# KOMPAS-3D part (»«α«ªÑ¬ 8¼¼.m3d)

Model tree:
1. Эскиз:1
2. Операция выдавливания:1
     Расстояние 1 = 8
3. Эскиз:2
4. Операция выдавливания:2
     Расстояние 1 = 1
5. Эскиз:3
6. Операция выдавливания:3
     Расстояние 1 = 2.5; Угол 1 = 8
7. Эскиз:4
8. Вырезать элемент выдавливания:1
     Расстояние 1 = 20
9. Эскиз:5
10. Вырезать элемент выдавливания:2
     Расстояние 1 = 3; Угол 1 = 19
11. Скругление:1
     Радиус = 1
12. Скругление:2
     Радиус = 1
13. Скругление:3
     Радиус = 1
14. Эскиз:6
15. Эскиз:7
16. Вырезать элемент выдавливания:3
     Расстояние 2 = 30; Расстояние 1 = 60
17. Эскиз:8
18. Вырезать элемент выдавливания:4
     Расстояние 2 = 30; Расстояние 1 = 60
19. Эскиз:9
20. Операция выдавливания:4
     Расстояние 1 = 10; Расстояние 2 = 62
21. Эскиз:10
22. Вырезать элемент выдавливания:5
     Расстояние 2 = 30; Расстояние 1 = 60
23. Скругление:4
     Радиус = 2
24. Скругление:5
     Радиус = 2
25. Эскиз:11
26. Вырезать элемент выдавливания:6
     Расстояние 1 = 10
27. Эскиз:12
28. Вырезать элемент выдавливания:7
     Расстояние 1 = 2.5; Угол 1 = 3
29. Эскиз:13
30. Вырезать элемент выдавливания:8
     Расстояние 2 = 40; Расстояние 1 = 30
31. Эскиз:14
32. Операция выдавливания:5
     Расстояние 1 = 10
33. Операция выдавливания:6
     Расстояние 1 = 2.5; Расстояние 2 = 5.94316
34. Эскиз:15
35. Вырезать элемент выдавливания:9
     Расстояние 1 = 20
36. Скругление:6
     Радиус = 1
37. Скругление:7
     Радиус = 1
